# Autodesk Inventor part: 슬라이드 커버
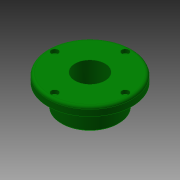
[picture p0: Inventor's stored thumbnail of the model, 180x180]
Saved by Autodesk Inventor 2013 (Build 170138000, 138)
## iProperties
Created: 2015-10
Part Number: 슬라이드 커버
Document SubType Name: Modeling
Designer: mdu
Density: 7.86 g/cm^3
Material: 강철, 연강
Mass: 598.523 g
Surface Area: 229.996 cm^2
Volume: 76.148 cm^3
Author: mdu
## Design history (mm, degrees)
sketch "스케치1"
  geometry: C1 r 47.5 at (0, 0); C2 r 32.5 at (0, 0); 1 further point
  constraints: 2 centre point, 2 coincident
  dimensions: "d33" = 95 diameter of C1; "d35" = 65 diameter of C2
extrude "돌출1" new body sketch "스케치1" distance "d0" = 10; taper "d1" = 0 deg
extrude "돌출2" join sketch "스케치1" distance "d2" = 25; taper "d3" = 0 deg
hole "구멍1" diameter "d6" = 36; stored, may be unused: countersink angle "d10" = 90 deg, drill point angle "d12" = 118 deg; dims "d7" = 6, "d8" = 4, "d9" = 2, "d11" = 8, "d41" = 10, "d42" = 10
sketch "스케치2" dims "d36" = 80
  geometry: 4 further points
  constraints: 2 coincident, 2 vertical alignment, 2 other
hole "구멍2" sketch "스케치2" at (0, 40) diameter "d13" = 4.5; stored, may be unused: countersink angle "d17" = 90 deg, drill point angle "d19" = 118 deg; dims "d14" = 6, "d15" = 8, "d16" = 4.4, "d18" = 8
fillet "모깎기1" dims "d23" = 3
chamfer "모따기1" distance "d24" = 1; stored, may be unused: second distance "d25" = 2, angle "d26" = 45 deg
sketch "스케치3"
  geometry: C1 r 26 at (0, 0); C2 r 19 at (0, 0) reference; 1 further point
  constraints: 1 centre point, 1 concentric
  dimensions: "d27" = 52 diameter of C1
extrude "돌출3" cut sketch "스케치3" distance "d28" = 10; taper "d29" = 0 deg
chamfer "모따기2" distance "d30" = 1; stored, may be unused: second distance "d31" = 2, angle "d32" = 45 deg
node "솔리드1"
pattern_circular "원형 패턴1" dims angle "d21" = 360 deg
